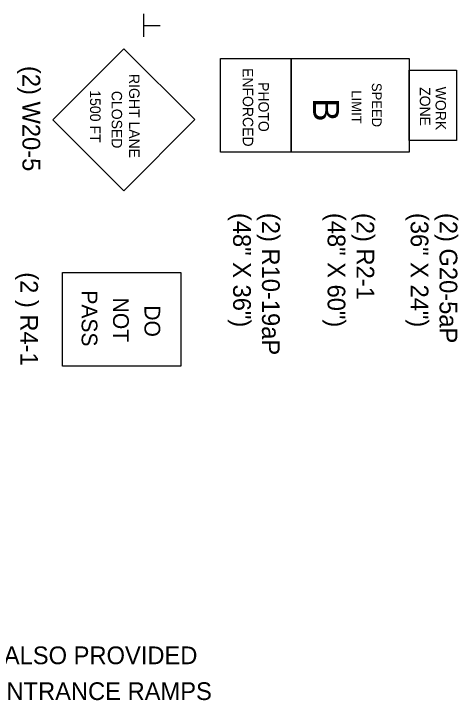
# Model space of a CAD drawing. Extents: x 1373848 to 1374003, y 380642 to 381248.
# Drawn here: x 1373899.64 to 1373914.69, y 381193.57 to 381216.82 of the extents above; entities that cross this region are included whole.
import ezdxf

# ---------------------------------------------------------------- set-up
doc = ezdxf.new("R2010")
doc.units = 0
doc.layers.add('Default', color=7, linetype='Continuous')

msp = doc.modelspace()

# ---------------------------------------------------------------- linework, layer by layer
at = {"layer": 'Default'}
for p, q in [((1373904.045, 381216.038), (1373904.045, 381216.821)), ((1373904.056, 381216.427), (1373904.59, 381216.427)), ((1373900.96, 381213.226), (1373903.361, 381215.636)), ((1373905.769, 381213.234), (1373903.361, 381215.636)), ((1373903.37, 381210.824), (1373900.96, 381213.226)), ((1373903.37, 381210.824), (1373905.769, 381213.234))]:
    msp.add_line(p, q, dxfattribs=at)
for points in [[(1373909.031, 381212.133), (1373906.633, 381212.133), (1373906.633, 381215.304), (1373909.031, 381215.304)], [(1373913.028, 381212.133), (1373909.031, 381212.133), (1373909.031, 381215.304), (1373913.028, 381215.304)], [(1373914.627, 381212.529), (1373913.028, 381212.529), (1373913.028, 381214.908), (1373914.627, 381214.908)], [(1373905.289, 381204.886), (1373901.292, 381204.886), (1373901.292, 381208.057), (1373905.289, 381208.057)]]:
    msp.add_lwpolyline(points, close=True, dxfattribs=at)

# ---------------------------------------------------------------- texts
for s, height, rotation, p in [('(2) W20-5', 0.6, 270, (1373899.933, 381215.052)), ('ENFORCED', 0.3544, 270.1004, (1373907.387, 381214.981)), ('RIGHT LANE', 0.3544, 270.1004, (1373903.54, 381214.779)), ('PHOTO', 0.3544, 270.1004, (1373907.92, 381214.507)), ('SPEED', 0.3303, 270, (1373911.761, 381214.479)), ('1500 FT', 0.3567, 270.0006, (1373902.22, 381214.231)), ('CLOSED', 0.3543, 270.1003, (1373902.95, 381214.208)), ('LIMIT', 0.3303, 270, (1373911.078, 381214.226)), ('ZONE', 0.3544, 270.1004, (1373913.383, 381214.335)), ('WORK', 0.3544, 270.1004, (1373913.915, 381214.35)), ('B', 0.885, 270, (1373909.768, 381213.959)), ('(48" X 36")', 0.6, 270, (1373907.064, 381210.075)), ('(2) R10-19aP', 0.6, 270, (1373908.042, 381210.075)), ('(48" X 60")', 0.6, 270, (1373910.263, 381210.075)), ('(2) R2-1', 0.6, 270, (1373911.241, 381210.075)), ('(36" X 24")', 0.6, 270, (1373913.075, 381210.075)), ('(2) G20-5aP', 0.6, 270, (1373914.053, 381210.075)), ('(2 ) R4-1', 0.6, 270, (1373899.858, 381208.067)), ('PASS', 0.5319, 270, (1373901.936, 381207.452)), ('NOT', 0.532, 270, (1373903, 381207.205)), ('DO', 0.532, 270, (1373904.064, 381206.945))]:
    msp.add_text(s, height=height, rotation=rotation, dxfattribs=at).set_placement(p)
for s, p in [('SPEED LIMIT SIGNS ARE ALSO PROVIDED', (1373889.493, 381194.795)), ('FOR PLACEMENT PAST ENTRANCE RAMPS ', (1373889.493, 381193.582))]:
    msp.add_text(s, height=0.6, dxfattribs=at).set_placement(p)

doc.saveas('drawing.dxf')
